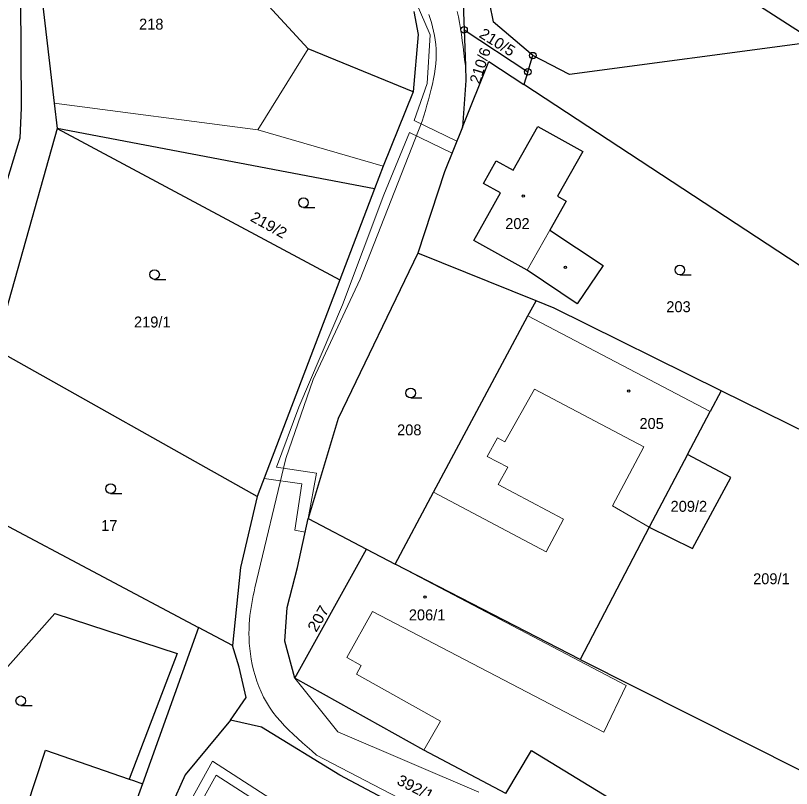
# Model space of a CAD drawing. Extents: x -504006 to -501322, y -1128098 to -1124665.
# Drawn here: x -502670.2 to -502549.5, y -1126824.4 to -1126704.2 of the extents above; entities that cross this region are included whole.
import ezdxf
from ezdxf.enums import TextEntityAlignment as Align

# ---------------------------------------------------------------- set-up
doc = ezdxf.new("R2010")
doc.units = 0
doc.header["$LTSCALE"] = 0.68
for name, color, linetype, lineweight in [('1', 7, 'Continuous', 25), ('13', 7, 'Continuous', 13), ('3', 7, 'Continuous', 25), ('4', 7, 'Continuous', 13), ('5', 7, 'Continuous', 25), ('8', 7, 'Continuous', 25)]:
    doc.layers.add(name, color=color, linetype=linetype, lineweight=lineweight)
doc.layers.add('2', color=7, linetype='Continuous')

msp = doc.modelspace()

# ---------------------------------------------------------------- linework, layer by layer
at = {"layer": '1'}
for p, q in [((-502667.59, -1126689.22), (-502664.19, -1126717.79)), ((-502624.72, -1126709.35), (-502642, -1126690.55)), ((-502545.88, -1126708.26), (-502566.86, -1126694.62)), ((-502669.46, -1126701.42), (-502669.34, -1126718.51)), ((-502600.61, -1126702.3), (-502600.46, -1126706.4)), ((-502608.28, -1126703.54), (-502607.58, -1126707.12)), ((-502589.76, -1126710.4), (-502595.93, -1126705.13)), ((-502600.46, -1126706.4), (-502600.25, -1126712)), ((-502600.46, -1126706.4), (-502590.55, -1126712.93)), ((-502607.58, -1126707.12), (-502608.39, -1126716.03)), ((-502545.88, -1126708.26), (-502584.04, -1126713.35)), ((-502608.39, -1126716.03), (-502624.72, -1126709.35)), ((-502590.55, -1126712.93), (-502589.76, -1126710.4)), ((-502584.04, -1126713.35), (-502589.76, -1126710.4)), ((-502600.68, -1126721.53), (-502596.6, -1126711.34)), ((-502596.6, -1126711.34), (-502591.17, -1126714.91)), ((-502600.25, -1126712), (-502600.17, -1126714.29)), ((-502590.55, -1126712.93), (-502591.17, -1126714.91)), ((-502600.17, -1126714.29), (-502600.68, -1126721.53)), ((-502534.85, -1126751.89), (-502591.17, -1126714.91)), ((-502608.39, -1126716.03), (-502613.03, -1126727.59)), ((-502664.19, -1126717.79), (-502663.74, -1126721.77)), ((-502669.34, -1126718.51), (-502669.57, -1126723.24)), ((-502600.68, -1126721.53), (-502603.48, -1126728.5)), ((-502592.81, -1126728.25), (-502588.97, -1126721.41)), ((-502588.97, -1126721.41), (-502582.01, -1126725.31)), ((-502663.74, -1126721.77), (-502673.41, -1126756.05)), ((-502663.74, -1126721.77), (-502619.78, -1126745.3)), ((-502614.38, -1126731.13), (-502663.74, -1126721.77)), ((-502669.57, -1126723.24), (-502678.64, -1126753.11)), ((-502582.01, -1126725.31), (-502585.94, -1126732.27)), ((-502597.43, -1126730.3), (-502595.47, -1126726.78)), ((-502595.47, -1126726.78), (-502592.81, -1126728.25)), ((-502613.03, -1126727.59), (-502614.38, -1126731.13)), ((-502603.48, -1126728.5), (-502607.63, -1126741.14)), ((-502614.38, -1126731.13), (-502619.78, -1126745.3)), ((-502594.77, -1126731.75), (-502597.43, -1126730.3)), ((-502598.94, -1126739.19), (-502594.77, -1126731.75)), ((-502585.94, -1126732.27), (-502584.58, -1126733.04)), ((-502584.58, -1126733.04), (-502587.13, -1126737.58)), ((-502587.13, -1126737.58), (-502578.85, -1126743.08)), ((-502590.64, -1126743.8), (-502598.94, -1126739.19)), ((-502607.63, -1126741.14), (-502620.03, -1126766.83)), ((-502589.27, -1126748.54), (-502607.63, -1126741.14)), ((-502578.85, -1126743.08), (-502582.85, -1126749.01)), ((-502582.85, -1126749.01), (-502590.64, -1126743.8)), ((-502619.78, -1126745.3), (-502632.62, -1126778.97)), ((-502590.52, -1126750.88), (-502589.27, -1126748.54)), ((-502586.45, -1126749.68), (-502589.27, -1126748.54)), ((-502560.46, -1126762.54), (-502586.45, -1126749.68)), ((-502605.19, -1126778.31), (-502590.52, -1126750.88)), ((-502632.62, -1126778.97), (-502673.41, -1126756.05)), ((-502560.46, -1126762.54), (-502562.16, -1126765.76)), ((-502545.19, -1126770.1), (-502560.46, -1126762.54)), ((-502565.72, -1126772.48), (-502562.16, -1126765.76)), ((-502620.03, -1126766.83), (-502624.71, -1126782.41)), ((-502565.72, -1126772.48), (-502571.68, -1126783.76)), ((-502558.99, -1126776.03), (-502565.72, -1126772.48)), ((-502564.93, -1126787.08), (-502558.99, -1126776.03)), ((-502632.62, -1126778.97), (-502635.21, -1126790.05)), ((-502611.17, -1126789.49), (-502605.19, -1126778.31)), ((-502678.41, -1126779.95), (-502641.75, -1126799.38)), ((-502626.35, -1126790.05), (-502624.71, -1126782.41)), ((-502624.71, -1126782.41), (-502615.62, -1126787.19)), ((-502571.68, -1126783.76), (-502582.38, -1126804.36)), ((-502571.68, -1126783.76), (-502564.93, -1126787.08)), ((-502626.79, -1126807.23), (-502615.62, -1126787.19)), ((-502615.62, -1126787.19), (-502611.17, -1126789.49)), ((-502635.21, -1126790.05), (-502636.45, -1126802.19)), ((-502627.99, -1126796.26), (-502626.35, -1126790.05)), ((-502582.38, -1126804.36), (-502611.17, -1126789.49)), ((-502628.34, -1126801.48), (-502627.99, -1126796.26)), ((-502681.9, -1126817.21), (-502664.13, -1126797.18)), ((-502664.13, -1126797.18), (-502645.09, -1126803.41)), ((-502641.75, -1126799.38), (-502650.47, -1126823.67)), ((-502636.45, -1126802.19), (-502641.75, -1126799.38)), ((-502635.44, -1126805.54), (-502636.45, -1126802.19)), ((-502626.79, -1126807.23), (-502628.34, -1126801.48)), ((-502645.09, -1126803.41), (-502652.57, -1126822.94)), ((-502582.38, -1126804.36), (-502548.07, -1126821.6)), ((-502634.33, -1126810.23), (-502635.44, -1126805.54)), ((-502606.73, -1126818.47), (-502626.79, -1126807.23)), ((-502636.8, -1126813.77), (-502634.33, -1126810.23)), ((-502636.8, -1126813.77), (-502643.86, -1126822.29)), ((-502631.96, -1126814.85), (-502636.8, -1126813.77)), ((-502619.79, -1126822.36), (-502631.96, -1126814.85)), ((-502669.47, -1126830.2), (-502665.54, -1126818.43)), ((-502665.54, -1126818.43), (-502652.57, -1126822.94)), ((-502593.99, -1126825.19), (-502606.73, -1126818.47)), ((-502643.86, -1126822.29), (-502646.85, -1126829.07)), ((-502610.4, -1126827.3), (-502619.79, -1126822.36)), ((-502652.57, -1126822.94), (-502651.87, -1126823.18)), ((-502650.47, -1126823.67), (-502652.24, -1126828.61)), ((-502651.87, -1126823.18), (-502650.47, -1126823.67))]:
    msp.add_line(p, q, dxfattribs=at)
for points in [[(-502603.68, -1126695.28), (-502597.1, -1126699.5), (-502595.93, -1126705.13)], [(-502593.99, -1126825.19), (-502589.96, -1126818.51), (-502558.71, -1126837.57)]]:
    msp.add_lwpolyline(points, dxfattribs=at)
at = {"layer": '13'}
msp.add_lwpolyline([(-502608.28, -1126703.54), (-502607.58, -1126707.12), (-502607.64, -1126707.77), (-502608.39, -1126716.03), (-502613.03, -1126727.59), (-502614.38, -1126731.13), (-502619.78, -1126745.3), (-502631.56, -1126776.18), (-502625.71, -1126777.03), (-502626.77, -1126784.22), (-502625.17, -1126784.55), (-502624.71, -1126782.41), (-502623.41, -1126775.35), (-502629.64, -1126774.44), (-502626.18, -1126765.09), (-502619.36, -1126749.15), (-502612.95, -1126732.04), (-502608.96, -1126722.37), (-502602.31, -1126725.58), (-502601.56, -1126723.72), (-502608.24, -1126720.5), (-502606.21, -1126714.77), (-502605.71, -1126707.2), (-502607.9, -1126702.14)], dxfattribs=at)
msp.add_lwpolyline([(-502614.72, -1126837.98), (-502614.15, -1126836.57), (-502639.56, -1126820.18), (-502650.61, -1126840.15), (-502652.25, -1126844.99), (-502652.46, -1126846.59), (-502651.75, -1126845.32), (-502639.03, -1126822.31)], close=True, dxfattribs=at)
at = {"layer": '3'}
for p, q in [((-502625.433, -1126734.03), (-502623.683, -1126734.03)), ((-502648.603, -1126745.21), (-502646.853, -1126745.21)), ((-502566.903, -1126744.49), (-502565.153, -1126744.49)), ((-502608.763, -1126763.65), (-502607.013, -1126763.65)), ((-502655.433, -1126778.53), (-502653.683, -1126778.53)), ((-502669.403, -1126811.52), (-502667.653, -1126811.52))]:
    msp.add_line(p, q, dxfattribs=at)
for centre in [(-502625.4329, -1126733.2798), (-502566.9029, -1126743.7398), (-502648.6029, -1126744.4598), (-502608.7629, -1126762.8998), (-502655.4329, -1126777.7798), (-502669.4029, -1126810.7698)]:
    msp.add_circle(centre, 0.75, dxfattribs=at)
at = {"layer": '4'}
for p, q in [((-502624.72, -1126709.35), (-502632.56, -1126721.95)), ((-502632.56, -1126721.95), (-502664.19, -1126717.79)), ((-502616.6, -1126745.2), (-502607, -1126720.6)), ((-502632.56, -1126721.95), (-502613.03, -1126727.59)), ((-502587.13, -1126737.58), (-502590.64, -1126743.8)), ((-502623.95, -1126760.8), (-502616.6, -1126745.2)), ((-502590.52, -1126750.88), (-502562.16, -1126765.76)), ((-502628.2, -1126773.1), (-502623.95, -1126760.8)), ((-502594.12, -1126770.5), (-502589.52, -1126762.28)), ((-502589.52, -1126762.28), (-502572.49, -1126771.26)), ((-502596.87, -1126772.76), (-502595.25, -1126769.87)), ((-502595.25, -1126769.87), (-502594.12, -1126770.5)), ((-502572.49, -1126771.26), (-502577.38, -1126780.45)), ((-502628.2, -1126773.1), (-502633, -1126793.2)), ((-502593.65, -1126774.45), (-502596.87, -1126772.76)), ((-502595.16, -1126777.11), (-502593.65, -1126774.45)), ((-502585.02, -1126782.49), (-502595.16, -1126777.11)), ((-502605.19, -1126778.31), (-502587.67, -1126787.57)), ((-502577.38, -1126780.45), (-502571.68, -1126783.76)), ((-502587.67, -1126787.57), (-502585.02, -1126782.49)), ((-502615.62, -1126787.19), (-502575.24, -1126808.41)), ((-502614.7, -1126796.9), (-502618.67, -1126804.04)), ((-502578.71, -1126815.65), (-502614.7, -1126796.9)), ((-502618.67, -1126804.04), (-502616.44, -1126805.3)), ((-502616.44, -1126805.3), (-502617.18, -1126806.61)), ((-502617.18, -1126806.61), (-502604.15, -1126813.95)), ((-502620.1, -1126815.6), (-502626.79, -1126807.23)), ((-502575.24, -1126808.41), (-502578.71, -1126815.65)), ((-502604.15, -1126813.95), (-502606.73, -1126818.47)), ((-502598.18, -1126825), (-502620.1, -1126815.6)), ((-502623.4, -1126819.2), (-502604.2, -1126829.2))]:
    msp.add_line(p, q, dxfattribs=at)
for points in [[(-502607, -1126720.6), (-502606.742, -1126719.77), (-502606.483, -1126718.931), (-502606.235, -1126718.105), (-502605.995, -1126717.281), (-502605.766, -1126716.452), (-502605.555, -1126715.637), (-502605.364, -1126714.829), (-502605.192, -1126714.019), (-502605.048, -1126713.227), (-502604.933, -1126712.443), (-502604.848, -1126711.661), (-502604.8, -1126710.9), (-502604.789, -1126710.151), (-502604.813, -1126709.406), (-502604.87, -1126708.683), (-502604.956, -1126707.973), (-502605.071, -1126707.269), (-502605.209, -1126706.588), (-502605.369, -1126705.92), (-502605.55, -1126705.26), (-502605.744, -1126704.623), (-502605.952, -1126704.002)], [(-502600.25, -1126712), (-502600.371, -1126711.011), (-502600.495, -1126710.015), (-502600.62, -1126709.037), (-502600.749, -1126708.072), (-502600.885, -1126707.111), (-502601.027, -1126706.18), (-502601.177, -1126705.273), (-502601.338, -1126704.382), (-502601.508, -1126703.532)], [(-502633, -1126793.2), (-502633.126, -1126793.796), (-502633.251, -1126794.402), (-502633.37, -1126795.005), (-502633.483, -1126795.615), (-502633.589, -1126796.242), (-502633.682, -1126796.873), (-502633.763, -1126797.518), (-502633.83, -1126798.187), (-502633.878, -1126798.867), (-502633.908, -1126799.568), (-502633.916, -1126800.3), (-502633.9, -1126801.05), (-502633.859, -1126801.826), (-502633.789, -1126802.636), (-502633.691, -1126803.455), (-502633.562, -1126804.289), (-502633.399, -1126805.143), (-502633.203, -1126805.993), (-502632.971, -1126806.844), (-502632.697, -1126807.703), (-502632.388, -1126808.544), (-502632.037, -1126809.374), (-502631.639, -1126810.197), (-502631.2, -1126810.99), (-502630.716, -1126811.759), (-502630.183, -1126812.514), (-502629.617, -1126813.24), (-502629.017, -1126813.946), (-502628.378, -1126814.645), (-502627.72, -1126815.32), (-502627.038, -1126815.983), (-502626.329, -1126816.644), (-502625.612, -1126817.288), (-502624.884, -1126817.926), (-502624.14, -1126818.568), (-502623.4, -1126819.2)]]:
    msp.add_lwpolyline(points, dxfattribs=at)
at = {"layer": '5'}
for centre in [(-502591.2568, -1126732.2592), (-502584.6968, -1126743.3292), (-502574.8568, -1126762.5892), (-502606.5168, -1126794.6392)]:
    msp.add_circle(centre, 0.175, dxfattribs=at)
at = {"layer": '8'}
for centre, radius in [((-502600.46, -1126706.3999), 0.5), ((-502600.46, -1126706.3999), 0.0303), ((-502589.76, -1126710.3999), 0.5), ((-502589.76, -1126710.3999), 0.0303), ((-502590.55, -1126712.9299), 0.5), ((-502590.55, -1126712.9299), 0.0303)]:
    msp.add_circle(centre, radius, dxfattribs=at)

# ---------------------------------------------------------------- texts
at = {"layer": '2'}
for s, p in [('218', (-502649.109, -1126706.365)), ('202', (-502592.159, -1126737.385)), ('203', (-502567.109, -1126750.315)), ('219/1', (-502648.95, -1126752.695)), ('205', (-502571.289, -1126768.485)), ('208', (-502608.979, -1126769.475)), ('209/2', (-502565.5, -1126781.365)), ('17', (-502655.639, -1126784.355)), ('209/1', (-502552.66, -1126792.635)), ('206/1', (-502606.21, -1126798.255))]:
    msp.add_text(s, height=1.7, dxfattribs=at).set_placement(p, align=Align.CENTER)
for s, rotation, width, p in [('210/5', 328, 1.05, (-502595.7259, -1126709.0329)), ('219/2', 331, 1.05, (-502631.2256, -1126737.4873)), ('207', 60, 1.1, (-502622.4066, -1126798.396))]:
    msp.add_text(s, height=1.7, rotation=rotation, dxfattribs=dict(at, width=width)).set_placement(p, align=Align.CENTER)
msp.add_text('210/6', height=1.7, rotation=72, dxfattribs=at).set_placement((-502597.152, -1126712.2167), align=Align.CENTER)
at = {"layer": '2', "width": 1.05}
msp.add_text('392/1', height=1.7, rotation=333, dxfattribs=at).set_placement((-502611.062, -1126823.678))

doc.saveas('drawing.dxf')
